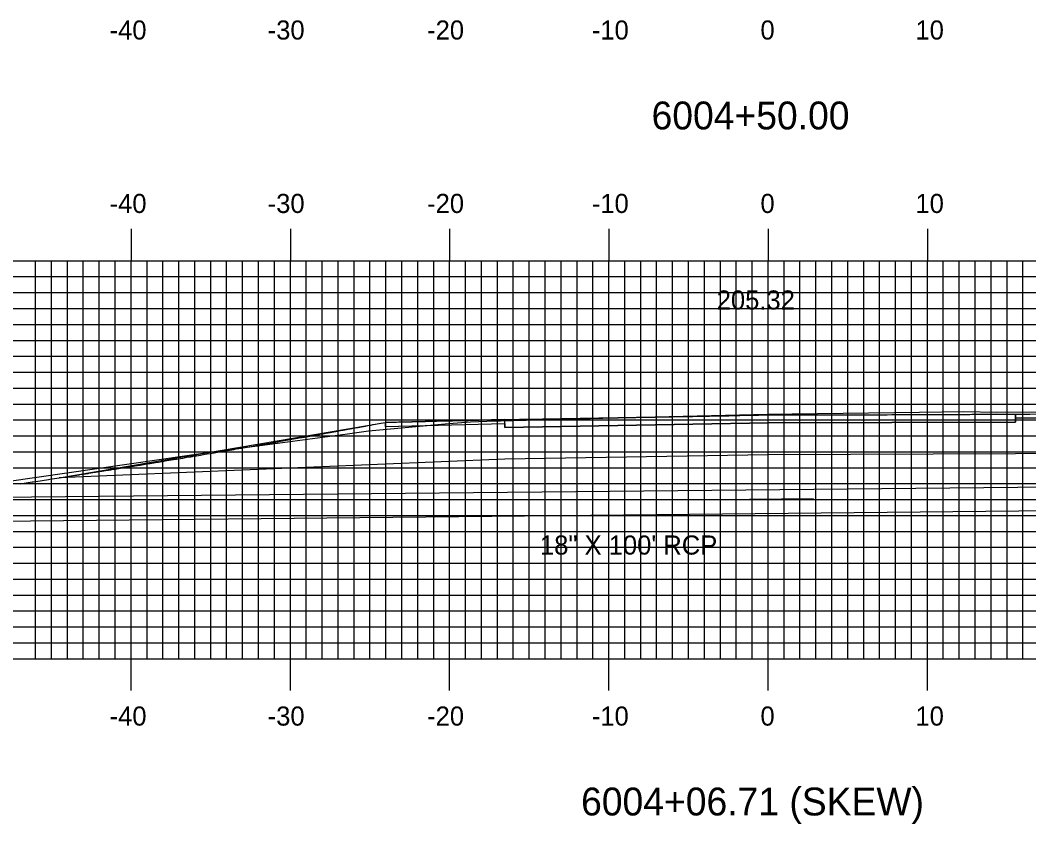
# Model space of a CAD drawing. Extents: x 852087 to 852430, y 366898 to 367118.
# Drawn here: x 852205.6 to 852268.9, y 366954.7 to 367005.2 of the extents above; entities that cross this region are included whole.
import ezdxf

# ---------------------------------------------------------------- set-up
doc = ezdxf.new("R2010")
doc.units = 0
for name, color, linetype in [('D_Drainage_Culvert', 7, 'Continuous'), ('D_Drainage_Text', 7, 'Continuous'), ('D_Roadway_Centerline', 7, 'Continuous'), ('D_Roadway_Edge_Shoulder', 7, 'Continuous'), ('D_Roadway_Edge_TW', 7, 'Continuous'), ('D_Roadway_SubGrade', 7, 'Continuous'), ('H_V ANNOTATION', 7, 'Continuous'), ('MAJOR', 7, 'Continuous'), ('MINOR', 7, 'Continuous'), ('S_Roadway_Centerline', 7, 'Continuous')]:
    doc.layers.add(name, color=color, linetype=linetype)

msp = doc.modelspace()

# ---------------------------------------------------------------- linework, layer by layer
at = {"layer": 'D_Drainage_Culvert'}
for p, q in [((852198.315, 366975.15), (852298.31, 366976.15)), ((852198.346, 366973.65), (852298.353, 366974.65)), ((852255.387, 366975.107), (852249.345, 366975.053))]:
    msp.add_line(p, q, dxfattribs=at)
at = {"layer": 'D_Roadway_Centerline'}
msp.add_lwpolyline([(852205.566, 366976.057), (852206.322, 366976.171), (852206.335, 366976.173), (852206.388, 366976.181), (852206.558, 366976.207), (852207.351, 366976.329), (852207.42, 366976.339), (852208.004, 366976.429), (852208.308, 366976.476), (852208.322, 366976.479), (852208.718, 366976.54), (852208.732, 366976.542), (852209.268, 366976.625), (852209.303, 366976.631), (852209.829, 366976.713), (852209.88, 366976.721), (852210.245, 366976.779), (852210.247, 366976.779), (852210.292, 366976.786), (852210.293, 366976.786), (852210.649, 366976.842), (852210.702, 366976.851), (852211.054, 366976.906), (852211.115, 366976.916), (852211.186, 366976.927), (852211.199, 366976.929), (852211.277, 366976.942), (852211.292, 366976.944), (852211.49, 366976.976), (852211.53, 366976.982), (852211.868, 366977.036), (852211.947, 366977.049), (852212.228, 366977.094), (852212.301, 366977.106), (852212.352, 366977.114), (852212.365, 366977.116), (852212.689, 366977.169), (852212.785, 366977.184), (852213.102, 366977.235), (852213.207, 366977.252), (852213.291, 366977.266), (852213.32, 366977.271), (852213.546, 366977.308), (852213.631, 366977.321), (852213.699, 366977.333), (852213.725, 366977.337), (852213.96, 366977.375), (852214.056, 366977.391), (852214.259, 366977.424), (852214.349, 366977.439), (852214.441, 366977.454), (852214.483, 366977.461), (852214.77, 366977.509), (852214.912, 366977.532), (852215.191, 366977.578), (852215.342, 366977.603), (852215.372, 366977.608), (852215.388, 366977.611), (852215.63, 366977.651), (852215.775, 366977.675), (852216.038, 366977.719), (852216.209, 366977.748), (852216.272, 366977.758), (852216.315, 366977.765), (852216.388, 366977.778), (852216.438, 366977.786), (852216.558, 366977.806), (852216.645, 366977.821), (852216.892, 366977.863), (852217.083, 366977.895), (852217.31, 366977.933), (852217.499, 366977.965), (852217.512, 366977.967), (852217.523, 366977.969), (852217.754, 366978.008), (852217.965, 366978.044), (852218.187, 366978.082), (852218.408, 366978.12), (852218.488, 366978.133), (852218.571, 366978.148), (852218.706, 366978.171), (852218.854, 366978.196), (852218.909, 366978.206), (852218.972, 366978.216), (852219.122, 366978.242), (852219.301, 366978.273), (852219.457, 366978.3), (852219.655, 366978.334), (852219.696, 366978.341), (852219.751, 366978.351), (852219.939, 366978.383), (852220.203, 366978.429), (852220.381, 366978.46), (852220.656, 366978.508), (852220.692, 366978.514), (852220.75, 366978.524), (852220.884, 366978.548), (852221.112, 366978.587), (852221.272, 366978.615), (852221.569, 366978.667), (852221.613, 366978.675), (852221.701, 366978.69), (852221.752, 366978.699), (852221.857, 366978.718), (852221.912, 366978.728), (852222.029, 366978.748), (852222.171, 366978.773), (852222.491, 366978.83), (852222.623, 366978.853), (852222.955, 366978.912), (852222.961, 366978.913), (852222.977, 366978.916), (852223.093, 366978.937), (852223.421, 366978.995), (852223.534, 366979.015), (852223.89, 366979.078), (852223.938, 366979.087), (852224.109, 366979.118), (852224.162, 366979.127), (852224.36, 366979.163), (852224.389, 366979.168), (852224.505, 366979.189), (852224.568, 366979.2), (852224.833, 366979.248), (852224.906, 366979.261), (852225.254, 366979.324), (852225.262, 366979.325), (852225.308, 366979.333), (852225.38, 366979.347), (852225.786, 366979.42), (852225.847, 366979.431), (852226.265, 366979.507), (852226.281, 366979.51), (852226.412, 366979.534), (852226.446, 366979.54), (852226.747, 366979.595), (852226.787, 366979.602), (852227.231, 366979.683), (852227.241, 366979.685), (852227.39, 366979.712), (852227.401, 366979.714), (852227.584, 366979.748), (852227.59, 366979.749), (852227.718, 366979.773), (852227.736, 366979.776), (852228.207, 366979.863), (852228.214, 366979.864), (852228.491, 366979.915), (852228.686, 366979.92), (852228.698, 366979.92), (852228.768, 366979.922), (852228.77, 366979.922), (852229.157, 366979.932), (852229.192, 366979.933), (852229.619, 366979.944), (852229.689, 366979.946), (852229.92, 366979.951), (852229.971, 366979.953), (852230.142, 366979.957), (852230.187, 366979.958), (852230.322, 366979.961), (852230.362, 366979.962), (852230.601, 366979.968), (852230.689, 366979.97), (852231.026, 366979.979), (852231.185, 366979.982), (852231.19, 366979.983), (852231.193, 366979.983), (852231.504, 366979.991), (852231.699, 366979.995), (852231.98, 366980.002), (852232.208, 366980.007), (852232.313, 366980.01), (852232.415, 366980.012), (852232.56, 366980.016), (852232.72, 366980.019), (852232.938, 366980.025), (852233.234, 366980.031), (852233.305, 366980.033), (852233.425, 366980.035), (852233.507, 366980.037), (852233.661, 366980.041), (852233.69, 366980.042), (852233.751, 366980.043), (852233.903, 366980.047), (852234.271, 366980.055), (852234.389, 366980.058), (852234.793, 366980.066), (852234.815, 366980.067), (852234.922, 366980.069), (852234.979, 366980.071), (852235.318, 366980.078), (852235.365, 366980.079), (852235.846, 366980.09), (852235.853, 366980.09), (852235.99, 366980.093), (852236.195, 366980.096), (852236.2, 366980.096), (852236.373, 366980.098), (852236.377, 366980.099), (852236.382, 366980.099), (852236.586, 366980.102), (852236.598, 366980.102), (852236.911, 366980.107), (852237.4, 366980.114), (852237.448, 366980.115), (852237.49, 366980.116), (852237.494, 366980.116), (852237.927, 366980.122), (852237.987, 366980.123), (852238.446, 366980.131), (852238.53, 366980.132), (852238.757, 366980.136), (852238.805, 366980.136), (852238.854, 366980.137), (852239.075, 366980.141), (852239.503, 366980.148), (852239.624, 366980.15), (852239.796, 366980.152), (852239.85, 366980.153), (852239.92, 366980.155), (852240.134, 366980.158), (852240.154, 366980.158), (852240.161, 366980.158), (852240.165, 366980.159), (852240.174, 366980.159), (852240.175, 366980.159), (852240.175, 366980.159), (852240.185, 366980.159), (852240.188, 366980.159), (852240.198, 366980.159), (852240.201, 366980.159), (852240.211, 366980.159), (852240.215, 366980.159), (852240.218, 366980.159), (852240.228, 366980.16), (852240.238, 366980.16), (852240.241, 366980.16), (852240.251, 366980.16), (852240.255, 366980.16), (852240.258, 366980.16), (852240.268, 366980.16), (852240.395, 366980.162), (852240.73, 366980.168), (852240.783, 366980.169), (852240.806, 366980.169), (852240.955, 366980.172), (852241.288, 366980.177), (852241.407, 366980.179), (852241.468, 366980.18), (852241.472, 366980.18), (852241.481, 366980.18), (852241.718, 366980.184), (852241.849, 366980.187), (852242.061, 366980.19), (852242.413, 366980.196), (852242.659, 366980.2), (852242.833, 366980.204), (852242.841, 366980.204), (852242.847, 366980.204), (852242.904, 366980.205), (852242.98, 366980.206), (852243.118, 366980.208), (852243.227, 366980.21), (852243.402, 366980.213), (852243.551, 366980.216), (852243.845, 366980.221), (852244.125, 366980.226), (852244.178, 366980.227), (852244.232, 366980.228), (852244.478, 366980.232), (852244.702, 366980.236), (852245.025, 366980.242), (852245.283, 366980.247), (852245.43, 366980.249), (852245.636, 366980.253), (852245.775, 366980.256), (852245.867, 366980.257), (852246.089, 366980.261), (852246.454, 366980.268), (852246.548, 366980.27), (852246.722, 366980.273), (852246.939, 366980.277), (852247.045, 366980.279), (852247.05, 366980.279), (852247.061, 366980.279), (852247.24, 366980.282), (852247.64, 366980.29), (852247.805, 366980.293), (852248.238, 366980.301), (852248.442, 366980.305), (852248.506, 366980.306), (852248.767, 366980.311), (852248.84, 366980.312), (852248.965, 366980.315), (852249.445, 366980.324), (852249.892, 366980.332), (852249.973, 366980.334), (852249.985, 366980.334), (852250.055, 366980.335), (852250.308, 366980.34), (852250.345, 366980.341), (852250.385, 366980.342), (852250.668, 366980.347), (852250.709, 366980.348), (852250.714, 366980.348), (852250.717, 366980.348), (852250.744, 366980.349), (852250.746, 366980.349), (852250.759, 366980.349), (852251.245, 366980.358), (852251.284, 366980.359), (852251.45, 366980.362), (852251.461, 366980.363), (852251.488, 366980.363), (852251.905, 366980.371), (852251.927, 366980.372), (852252.529, 366980.384), (852252.531, 366980.384), (852252.973, 366980.384), (852252.978, 366980.384), (852253.158, 366980.384), (852253.738, 366980.384), (852253.79, 366980.385), (852253.817, 366980.385), (852254.105, 366980.385), (852254.14, 366980.385), (852254.426, 366980.385), (852254.496, 366980.385), (852254.507, 366980.385), (852254.975, 366980.386), (852255.067, 366980.386), (852255.58, 366980.387), (852255.712, 366980.387), (852255.789, 366980.388), (852256.065, 366980.388), (852256.136, 366980.388), (852256.36, 366980.389), (852256.826, 366980.389), (852257.013, 366980.39), (852257.211, 366980.391), (852257.648, 366980.391), (852257.656, 366980.391), (852257.671, 366980.391), (852257.89, 366980.392), (852258.012, 366980.392), (852258.211, 366980.393), (852258.332, 366980.393), (852258.6, 366980.394), (852258.998, 366980.395), (852259.111, 366980.395), (852259.256, 366980.396), (852259.479, 366980.396), (852259.669, 366980.397), (852260.009, 366980.398), (852260.343, 366980.399), (852260.636, 366980.4), (852260.891, 366980.401), (852260.95, 366980.401), (852261.023, 366980.402), (852261.311, 366980.402), (852261.707, 366980.404), (852261.85, 366980.405), (852262.077, 366980.406), (852262.281, 366980.407), (852262.396, 366980.407), (852262.45, 366980.407), (852262.552, 366980.407), (852262.917, 366980.409), (852263.089, 366980.41), (852263.295, 366980.41), (852263.787, 366980.413), (852263.904, 366980.413), (852264.241, 366980.415), (852264.434, 366980.416), (852264.49, 366980.416), (852264.64, 366980.416), (852265.198, 366980.419), (852265.319, 366980.42), (852265.911, 366980.423), (852265.952, 366980.423), (852265.958, 366980.423), (852266.003, 366980.423), (852266.312, 366980.425), (852266.346, 366980.425), (852266.629, 366980.427), (852267.319, 366980.43), (852267.352, 366980.43), (852267.697, 366980.432), (852267.705, 366980.432), (852267.713, 366980.432), (852268.066, 366980.434), (852268.08, 366980.435), (852268.083, 366980.435), (852268.814, 366980.439), (852268.963, 366980.44)], dxfattribs=at)
at = {"layer": 'D_Roadway_Edge_Shoulder'}
for points in [[(852268.066, 366980.434), (852272.012, 366980.459), (852272.012, 366980.209), (852268.066, 366980.184)], [(852235.989, 366980.093), (852228.491, 366979.915), (852228.491, 366979.665), (852235.989, 366979.843)]]:
    msp.add_lwpolyline(points, close=True, dxfattribs=at)
at = {"layer": 'D_Roadway_Edge_TW'}
msp.add_lwpolyline([(852235.989, 366979.593), (852235.989, 366980.093), (852252.531, 366980.384), (852268.066, 366980.434), (852268.066, 366979.934), (852252.531, 366979.884)], close=True, dxfattribs=at)
at = {"layer": 'D_Roadway_SubGrade'}
msp.add_lwpolyline([(852235.989, 366977.593), (852208.004, 366976.429), (852228.491, 366979.915), (852228.491, 366979.665), (852235.989, 366979.843), (852235.989, 366979.593), (852252.531, 366979.884), (852268.066, 366979.934), (852268.066, 366980.184), (852272.012, 366980.209), (852272.012, 366980.459), (852285.591, 366978.068), (852268.066, 366977.934), (852252.531, 366977.884)], close=True, dxfattribs=at)
at = {"layer": 'MAJOR'}
for p, q in [((852212.531, 366992.071), (852212.531, 366990.067)), ((852222.531, 366992.071), (852222.531, 366990.067)), ((852232.531, 366992.071), (852232.531, 366990.067)), ((852242.531, 366992.071), (852242.531, 366990.067)), ((852252.531, 366992.071), (852252.531, 366990.067)), ((852262.531, 366992.071), (852262.531, 366990.067)), ((852112.531, 366990.067), (852392.531, 366990.067)), ((852112.531, 366990.067), (852392.531, 366990.067)), ((852212.531, 366965.067), (852212.531, 366990.067)), ((852222.531, 366965.067), (852222.531, 366990.067)), ((852232.531, 366965.067), (852232.531, 366990.067)), ((852242.531, 366965.067), (852242.531, 366990.067)), ((852252.531, 366965.067), (852252.531, 366990.067)), ((852262.531, 366965.067), (852262.531, 366990.067)), ((852112.531, 366985.067), (852392.531, 366985.067)), ((852112.531, 366980.067), (852392.531, 366980.067)), ((852112.531, 366975.067), (852392.531, 366975.067)), ((852112.531, 366970.067), (852392.531, 366970.067)), ((852112.531, 366965.067), (852392.531, 366965.067)), ((852112.531, 366965.067), (852392.531, 366965.067)), ((852212.531, 366963.063), (852212.531, 366965.067)), ((852222.531, 366963.063), (852222.531, 366965.067)), ((852232.531, 366963.063), (852232.531, 366965.067)), ((852242.531, 366963.063), (852242.531, 366965.067)), ((852252.531, 366963.063), (852252.531, 366965.067)), ((852262.531, 366963.063), (852262.531, 366965.067))]:
    msp.add_line(p, q, dxfattribs=at)
at = {"layer": 'MINOR'}
for p, q in [((852206.531, 366965.067), (852206.531, 366990.067)), ((852207.531, 366965.067), (852207.531, 366990.067)), ((852208.531, 366965.067), (852208.531, 366990.067)), ((852209.531, 366965.067), (852209.531, 366990.067)), ((852210.531, 366965.067), (852210.531, 366990.067)), ((852211.531, 366965.067), (852211.531, 366990.067)), ((852213.531, 366965.067), (852213.531, 366990.067)), ((852214.531, 366965.067), (852214.531, 366990.067)), ((852215.531, 366965.067), (852215.531, 366990.067)), ((852216.531, 366965.067), (852216.531, 366990.067)), ((852217.531, 366965.067), (852217.531, 366990.067)), ((852218.531, 366965.067), (852218.531, 366990.067)), ((852219.531, 366965.067), (852219.531, 366990.067)), ((852220.531, 366965.067), (852220.531, 366990.067)), ((852221.531, 366965.067), (852221.531, 366990.067)), ((852223.531, 366965.067), (852223.531, 366990.067)), ((852224.531, 366965.067), (852224.531, 366990.067)), ((852225.531, 366965.067), (852225.531, 366990.067)), ((852226.531, 366965.067), (852226.531, 366990.067)), ((852227.531, 366965.067), (852227.531, 366990.067)), ((852228.531, 366965.067), (852228.531, 366990.067)), ((852229.531, 366965.067), (852229.531, 366990.067)), ((852230.531, 366965.067), (852230.531, 366990.067)), ((852231.531, 366965.067), (852231.531, 366990.067)), ((852233.531, 366965.067), (852233.531, 366990.067)), ((852234.531, 366965.067), (852234.531, 366990.067)), ((852235.531, 366965.067), (852235.531, 366990.067)), ((852236.531, 366965.067), (852236.531, 366990.067)), ((852237.531, 366965.067), (852237.531, 366990.067)), ((852238.531, 366965.067), (852238.531, 366990.067)), ((852239.531, 366965.067), (852239.531, 366990.067)), ((852240.531, 366965.067), (852240.531, 366990.067)), ((852241.531, 366965.067), (852241.531, 366990.067)), ((852243.531, 366965.067), (852243.531, 366990.067)), ((852244.531, 366965.067), (852244.531, 366990.067)), ((852245.531, 366965.067), (852245.531, 366990.067)), ((852246.531, 366965.067), (852246.531, 366990.067)), ((852247.531, 366965.067), (852247.531, 366990.067)), ((852248.531, 366965.067), (852248.531, 366990.067)), ((852249.531, 366965.067), (852249.531, 366990.067)), ((852250.531, 366965.067), (852250.531, 366990.067)), ((852251.531, 366965.067), (852251.531, 366990.067)), ((852253.531, 366965.067), (852253.531, 366990.067)), ((852254.531, 366965.067), (852254.531, 366990.067)), ((852255.531, 366965.067), (852255.531, 366990.067)), ((852256.531, 366965.067), (852256.531, 366990.067)), ((852257.531, 366965.067), (852257.531, 366990.067)), ((852258.531, 366965.067), (852258.531, 366990.067)), ((852259.531, 366965.067), (852259.531, 366990.067)), ((852260.531, 366965.067), (852260.531, 366990.067)), ((852261.531, 366965.067), (852261.531, 366990.067)), ((852263.531, 366965.067), (852263.531, 366990.067)), ((852264.531, 366965.067), (852264.531, 366990.067)), ((852265.531, 366965.067), (852265.531, 366990.067)), ((852266.531, 366965.067), (852266.531, 366990.067)), ((852267.531, 366965.067), (852267.531, 366990.067)), ((852268.531, 366965.067), (852268.531, 366990.067)), ((852112.531, 366989.067), (852392.531, 366989.067)), ((852112.531, 366988.067), (852392.531, 366988.067)), ((852112.531, 366987.067), (852392.531, 366987.067)), ((852112.531, 366986.067), (852392.531, 366986.067)), ((852112.531, 366984.067), (852392.531, 366984.067)), ((852112.531, 366983.067), (852392.531, 366983.067)), ((852112.531, 366982.067), (852392.531, 366982.067)), ((852112.531, 366981.067), (852392.531, 366981.067)), ((852112.531, 366979.067), (852392.531, 366979.067)), ((852112.531, 366978.067), (852392.531, 366978.067)), ((852112.531, 366977.067), (852392.531, 366977.067)), ((852112.531, 366976.067), (852392.531, 366976.067)), ((852112.531, 366974.067), (852392.531, 366974.067)), ((852112.531, 366973.067), (852392.531, 366973.067)), ((852112.531, 366972.067), (852392.531, 366972.067)), ((852112.531, 366971.067), (852392.531, 366971.067)), ((852112.531, 366969.067), (852392.531, 366969.067)), ((852112.531, 366968.067), (852392.531, 366968.067)), ((852112.531, 366967.067), (852392.531, 366967.067)), ((852112.531, 366966.067), (852392.531, 366966.067))]:
    msp.add_line(p, q, dxfattribs=at)
at = {"layer": 'S_Roadway_Centerline'}
msp.add_lwpolyline([(852204.722, 366976.201), (852217.909, 366978.1), (852221.092, 366978.515), (852226.113, 366979.195), (852227.446, 366979.391), (852232.479, 366979.837), (852233.853, 366979.956), (852234.858, 366979.986), (852235.723, 366980.007), (852244.56, 366980.233), (852253.364, 366980.443), (852253.628, 366980.432), (852254.05, 366980.459), (852262.041, 366980.555), (852264.82, 366980.59), (852266.889, 366980.55), (852273.177, 366980.595)], dxfattribs=at)

# ---------------------------------------------------------------- texts
at = {"layer": 'D_Drainage_Text'}
msp.add_text('18" X 100\' RCP', height=1.2, dxfattribs=at).set_placement((852238.205, 366971.609))
at = {"layer": 'H_V ANNOTATION'}
for s, height, p in [('-40', 1.2, (852211.182, 367003.961)), ('-30', 1.2, (852221.107, 367003.961)), ('-20', 1.2, (852231.118, 367003.961)), ('-10', 1.2, (852241.461, 367003.961)), ('0', 1.2, (852252.049, 367003.961)), ('10', 1.2, (852261.782, 367003.961)), ('6004+50.00', 1.75, (852245.212, 366998.317)), ('-40', 1.2, (852211.182, 366993.067)), ('-30', 1.2, (852221.107, 366993.067)), ('-20', 1.2, (852231.118, 366993.067)), ('-10', 1.2, (852241.461, 366993.067)), ('0', 1.2, (852252.049, 366993.067)), ('10', 1.2, (852261.782, 366993.067)), ('205.32', 1.2, (852249.303, 366987.003)), ('-40', 1.2, (852211.182, 366960.867)), ('-30', 1.2, (852221.107, 366960.867)), ('-20', 1.2, (852231.118, 366960.867)), ('-10', 1.2, (852241.461, 366960.867)), ('0', 1.2, (852252.049, 366960.867)), ('10', 1.2, (852261.782, 366960.867)), ('6004+06.71 (SKEW)', 1.74996, (852240.787, 366955.223))]:
    msp.add_text(s, height=height, dxfattribs=at).set_placement(p)

doc.saveas('drawing.dxf')
